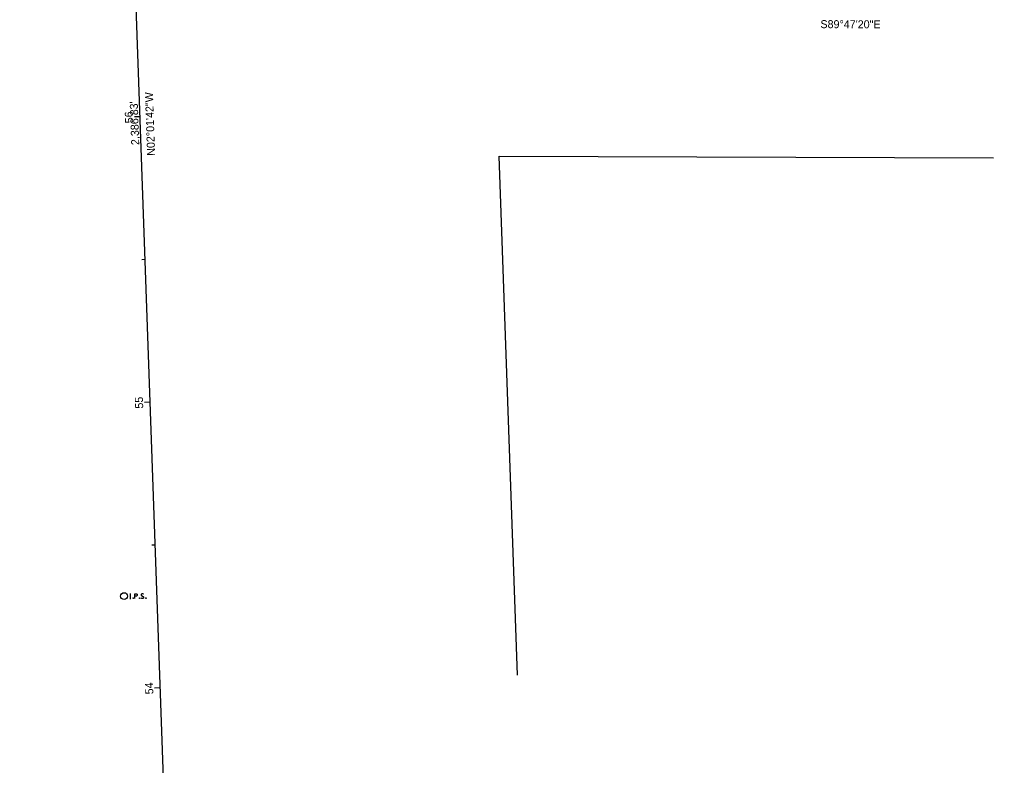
# Model space of a CAD drawing. Extents: x 146022 to 147490, y 436269 to 440659.
# Drawn here: x 146946.3 to 147286.9, y 438364.7 to 438625.8 of the extents above; entities that cross this region are included whole.
import ezdxf

# ---------------------------------------------------------------- set-up
doc = ezdxf.new("R2010")
doc.units = 0
for name, color, linetype in [('GE_X_Alignment_100_Bearings', 7, 'Continuous'), ('RW_X_CL', 7, 'Continuous'), ('RW_X_CL_100_Bearings', 7, 'Continuous'), ('RW_X_CL_100_Distances', 7, 'Continuous'), ('RW_X_CL_100_Stations', 7, 'Continuous'), ('RW_X_Esmt_SH', 7, 'Continuous'), ('RW_X_Fee_WL', 7, 'Continuous'), ('SV_P_Mon_Cells_Set', 7, 'Continuous')]:
    doc.layers.add(name, color=color, linetype=linetype)

msp = doc.modelspace()

# ---------------------------------------------------------------- linework, layer by layer
at = {"layer": 'RW_X_CL'}
msp.add_line((147030.73, 437397.38), (146946.25, 439782.71), dxfattribs=at)
at = {"layer": 'RW_X_CL_100_Stations'}
for p, q in [((146988.43, 438591.78), (146986.43, 438591.71)), ((146990.2, 438541.81), (146989, 438541.77)), ((146991.97, 438491.84), (146989.97, 438491.77)), ((146993.74, 438441.87), (146992.54, 438441.83)), ((146995.51, 438391.91), (146993.51, 438391.84))]:
    msp.add_line(p, q, dxfattribs=at)
at = {"layer": 'RW_X_Esmt_SH'}
msp.add_line((147114, 438578.02), (147286.94, 438577.38), dxfattribs=at)
at = {"layer": 'RW_X_Fee_WL'}
msp.add_line((147120.43, 438396.33), (147114, 438578.02), dxfattribs=at)
at = {"layer": 'SV_P_Mon_Cells_Set'}
for points in [[(146984.86, 438424.8), (146985.21, 438424.8)], [(146985.04, 438423.2), (146985.04, 438424.8)], [(146986.6, 438423.2), (146986.6, 438424.8), (146987.13, 438424.8), (146987.19, 438424.79), (146987.27, 438424.76), (146987.3, 438424.74), (146987.33, 438424.71), (146987.38, 438424.65), (146987.41, 438424.59), (146987.43, 438424.49), (146987.43, 438424.34), (146987.42, 438424.29), (146987.4, 438424.21), (146987.35, 438424.12), (146987.31, 438424.08), (146987.28, 438424.06), (146987.22, 438424.03), (146987.13, 438424.02), (146986.6, 438424.02)], [(146989.61, 438424.69), (146989.59, 438424.71), (146989.56, 438424.74), (146989.46, 438424.78), (146989.34, 438424.8), (146989.25, 438424.8), (146989.22, 438424.8), (146989.07, 438424.76), (146988.95, 438424.69), (146988.87, 438424.59), (146988.85, 438424.49), (146988.85, 438424.41), (146988.87, 438424.31), (146988.96, 438424.22), (146989.57, 438423.84), (146989.62, 438423.79), (146989.65, 438423.74), (146989.67, 438423.67), (146989.67, 438423.59), (146989.66, 438423.52), (146989.65, 438423.47), (146989.62, 438423.4), (146989.6, 438423.35), (146989.58, 438423.32), (146989.55, 438423.28), (146989.51, 438423.25), (146989.47, 438423.23), (146989.44, 438423.21), (146989.34, 438423.2), (146989.18, 438423.2), (146989.08, 438423.23), (146988.94, 438423.32), (146988.85, 438423.39)], [(146984.86, 438423.2), (146985.21, 438423.2)], [(146986, 438423.42), (146986.05, 438423.42), (146986.09, 438423.39), (146986.12, 438423.34), (146986.12, 438423.28), (146986.09, 438423.23), (146986.05, 438423.2), (146986, 438423.2), (146985.96, 438423.23), (146985.93, 438423.28), (146985.93, 438423.34), (146985.96, 438423.39), (146986, 438423.42)], [(146988.25, 438423.42), (146988.3, 438423.42), (146988.33, 438423.39), (146988.37, 438423.34), (146988.37, 438423.28), (146988.33, 438423.23), (146988.3, 438423.2), (146988.25, 438423.2), (146988.21, 438423.23), (146988.18, 438423.28), (146988.18, 438423.34), (146988.21, 438423.39), (146988.25, 438423.42)], [(146990.43, 438423.42), (146990.48, 438423.42), (146990.52, 438423.39), (146990.55, 438423.34), (146990.55, 438423.28), (146990.52, 438423.23), (146990.48, 438423.2), (146990.43, 438423.2), (146990.4, 438423.23), (146990.36, 438423.28), (146990.36, 438423.34), (146990.4, 438423.39), (146990.43, 438423.42)]]:
    msp.add_lwpolyline(points, dxfattribs=at)
msp.add_circle((146982.84, 438424), 1.2, dxfattribs=at)

# ---------------------------------------------------------------- texts
at = {"layer": 'GE_X_Alignment_100_Bearings'}
msp.add_text('S89°47\'20"E', height=2.8, rotation=359.7889, dxfattribs=at).set_placement((147226.4, 438622.81))
at = {"layer": 'RW_X_CL_100_Bearings'}
msp.add_text('N02°01\'42"W', height=2.8, rotation=92.0283, dxfattribs=at).set_placement((146993.71, 438578.19))
at = {"layer": 'RW_X_CL_100_Distances'}
msp.add_text("2,386.83'", height=2.8, rotation=92.0283, dxfattribs=at).set_placement((146988.15, 438581.94))
at = {"layer": 'RW_X_CL_100_Stations'}
for s, p in [('56', (146986.01, 438589.56)), ('55', (146989.54, 438489.67)), ('54', (146993.09, 438389.66))]:
    msp.add_text(s, height=2.8, rotation=92.0283, dxfattribs=at).set_placement(p)

doc.saveas('drawing.dxf')
